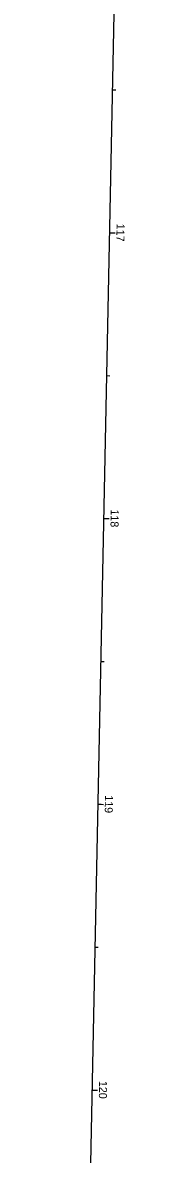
# Model space of a CAD drawing. Extents: x 1392427 to 1392809, y 435950 to 439080.
# Drawn here: x 1392717.3 to 1392763.4, y 437121.5 to 437517.5 of the extents above; entities that cross this region are included whole.
import ezdxf

# ---------------------------------------------------------------- set-up
doc = ezdxf.new("R2010")
doc.units = 0
for name, color, linetype in [('Default', 7, 'Continuous'), ('PV_X_Curb', 7, 'Continuous'), ('RD_X_Cells', 7, 'Continuous'), ('RW_X_CL', 7, 'Continuous'), ('RW_X_CL_100_Stations', 7, 'Continuous'), ('SV_X_Mon_Cells_Found', 7, 'Continuous')]:
    doc.layers.add(name, color=color, linetype=linetype)

msp = doc.modelspace()

# ---------------------------------------------------------------- linework, layer by layer
at = {"layer": 'Default'}
msp.add_line((1392763.4, 438217.67), (1392717.33, 435953.92), dxfattribs=at)
at = {"layer": 'PV_X_Curb'}
for p, q in [((1392747.65, 437443.93), (1392748.85, 437443.91)), ((1392745.62, 437343.95), (1392746.82, 437343.93)), ((1392743.58, 437243.97), (1392744.78, 437243.95)), ((1392741.55, 437143.99), (1392743.55, 437143.95))]:
    msp.add_line(p, q, dxfattribs=at)
at = {"layer": 'RD_X_Cells'}
msp.add_line((1392741.55, 437143.99), (1392743.55, 437143.95), dxfattribs=at)
at = {"layer": 'RW_X_CL'}
msp.add_line((1392763.4, 438217.67), (1392717.33, 435953.92), dxfattribs=at)
msp.add_line((1392763.4, 438217.67), (1392717.33, 435953.92), dxfattribs=at)
at = {"layer": 'RW_X_CL_100_Stations'}
for p, q in [((1392748.67, 437493.92), (1392749.87, 437493.9)), ((1392747.65, 437443.93), (1392749.65, 437443.89)), ((1392746.64, 437393.94), (1392747.84, 437393.92)), ((1392745.62, 437343.95), (1392747.62, 437343.91)), ((1392744.6, 437293.96), (1392745.8, 437293.94)), ((1392743.58, 437243.97), (1392745.58, 437243.93)), ((1392742.57, 437193.98), (1392743.77, 437193.96)), ((1392741.55, 437143.99), (1392743.55, 437143.95))]:
    msp.add_line(p, q, dxfattribs=at)
at = {"layer": 'SV_X_Mon_Cells_Found'}
for p, q in [((1392747.65, 437443.93), (1392748.85, 437443.91)), ((1392745.62, 437343.95), (1392746.82, 437343.93)), ((1392743.58, 437243.97), (1392744.78, 437243.95)), ((1392741.55, 437143.99), (1392743.55, 437143.95))]:
    msp.add_line(p, q, dxfattribs=at)

# ---------------------------------------------------------------- texts
at = {"layer": 'PV_X_Curb'}
msp.add_text('120', height=2.8, rotation=268.834, dxfattribs=at).set_placement((1392744.11, 437147.21))
at = {"layer": 'RD_X_Cells'}
msp.add_text('120', height=2.8, rotation=268.834, dxfattribs=at).set_placement((1392744.11, 437147.21))
at = {"layer": 'RW_X_CL_100_Stations'}
for s, p in [('117', (1392750.22, 437447.12)), ('118', (1392748.18, 437347.15)), ('119', (1392746.15, 437247.15)), ('120', (1392744.11, 437147.21))]:
    msp.add_text(s, height=2.8, rotation=268.834, dxfattribs=at).set_placement(p)
at = {"layer": 'SV_X_Mon_Cells_Found'}
msp.add_text('120', height=2.8, rotation=268.834, dxfattribs=at).set_placement((1392744.11, 437147.21))

doc.saveas('drawing.dxf')
